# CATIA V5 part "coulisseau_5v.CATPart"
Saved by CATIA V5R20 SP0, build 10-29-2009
Part number: coulisseau_5v
Bounding box of the stored display mesh (mm): x 111.543 to 150.007, y -36.794 to 1.67, z 83.509 to 90.176
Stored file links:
  D:\ecole\thinkmotion\IAO\coulisseau_5v.CATPart
  D:\ecole\thinkmotion\IAO\mecanisme coulisseau.CATProduct
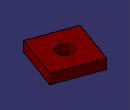
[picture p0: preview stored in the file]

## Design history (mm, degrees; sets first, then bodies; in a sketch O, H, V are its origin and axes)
External parameters (linked from other documents)
  External.rayon_pivot_bielle = 5 mm
Set1
  Plane1: linked copy from another document
  Point1: linked copy from another document
  Point2: linked copy from another document
  Plane2: linked copy from another document
  Point3: linked copy from another document
  Plane3: linked copy from another document
Body1 (main body)
  Sketch1 on Plane1, origin (0, 0, 83.509), H (1, 0, 0), V (0, 1, 0)
    line L1 (111.5428, -26.5131) -> (139.7261, -36.7941)
    line L2 (139.7261, -36.7941) -> (150.0071, -8.6108)
    line L3 (150.0071, -8.6108) -> (121.8238, 1.6702)
    line L4 (121.8238, 1.6702) -> (111.5428, -26.5131)
    point P2 (139.7261, -36.7941)
    point P4 (121.8238, 1.6702)
    reference projected point E1 (139.7261, -36.7941) from Point1
    reference projected point E2 (121.8238, 1.6702) from Point2
    reference intersected line E3 through (-79.7376, -550.8704) direction (0.3427, 0.9394) from Plane3
    coincidence: P2 E1, P4 E2, E3 L4
    parallelism: L2 L4
    perpendicularity: L3 L2, L1 L2
  Pad1: profile Sketch1, direction (0, 0, 1), up to Plane2
  Sketch2 on start face of Pad1, origin (15, 15, 83.509), H (1, 0, 0), V (0, -1, 0)
    point P1 (115.775, 32.5619)
    reference projected point E1 (115.775, 32.5619) from Point3
    coincidence: E1 P1
  Hole1: placed by Sketch2, at (130.775, -17.5619, 83.509) direction (0, 0, 1), diameter 10 {= External.rayon_pivot_bielle *2}, up to Plane2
